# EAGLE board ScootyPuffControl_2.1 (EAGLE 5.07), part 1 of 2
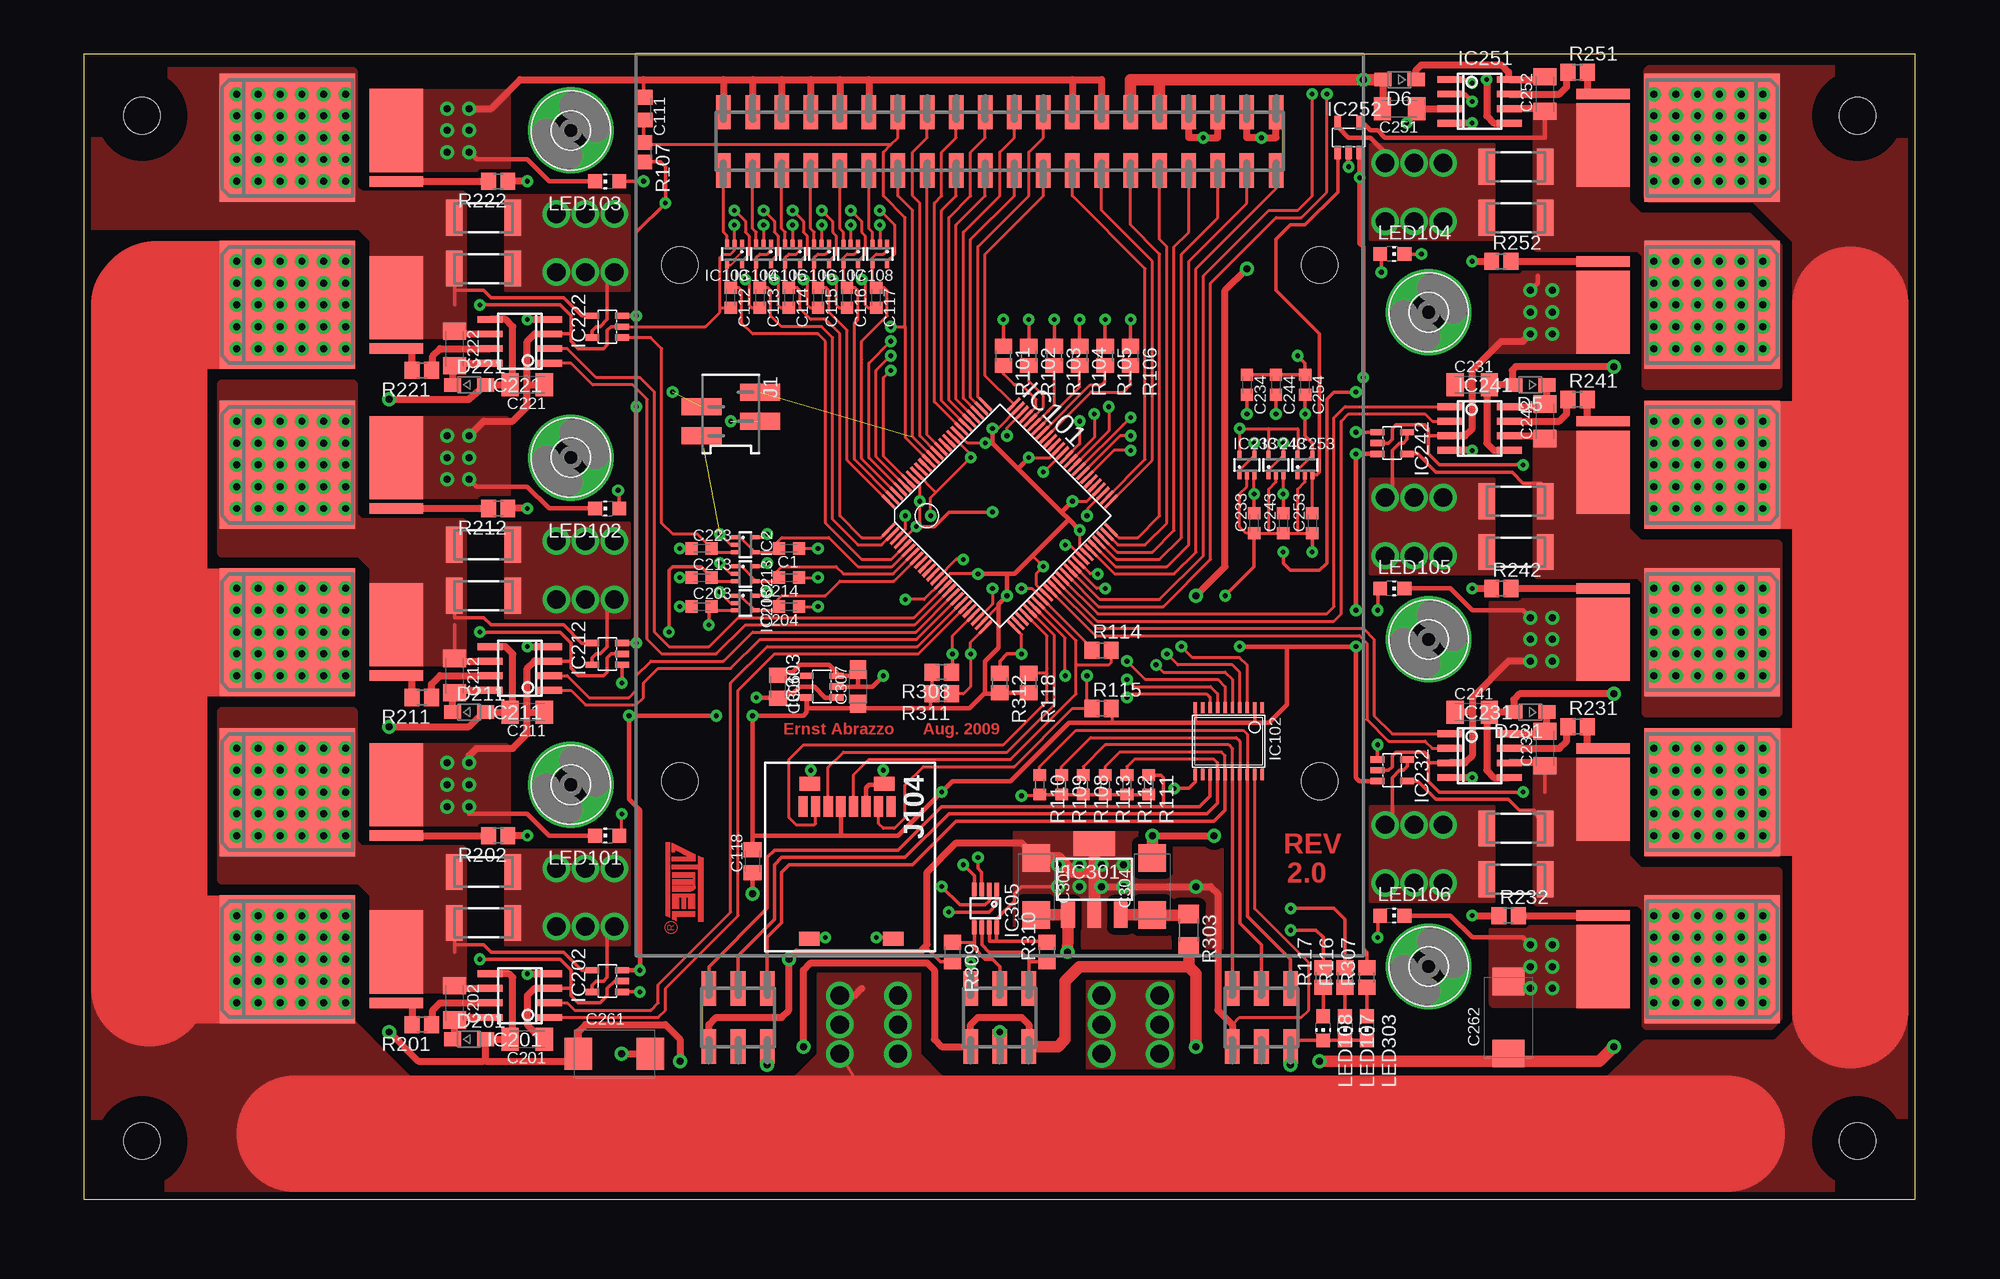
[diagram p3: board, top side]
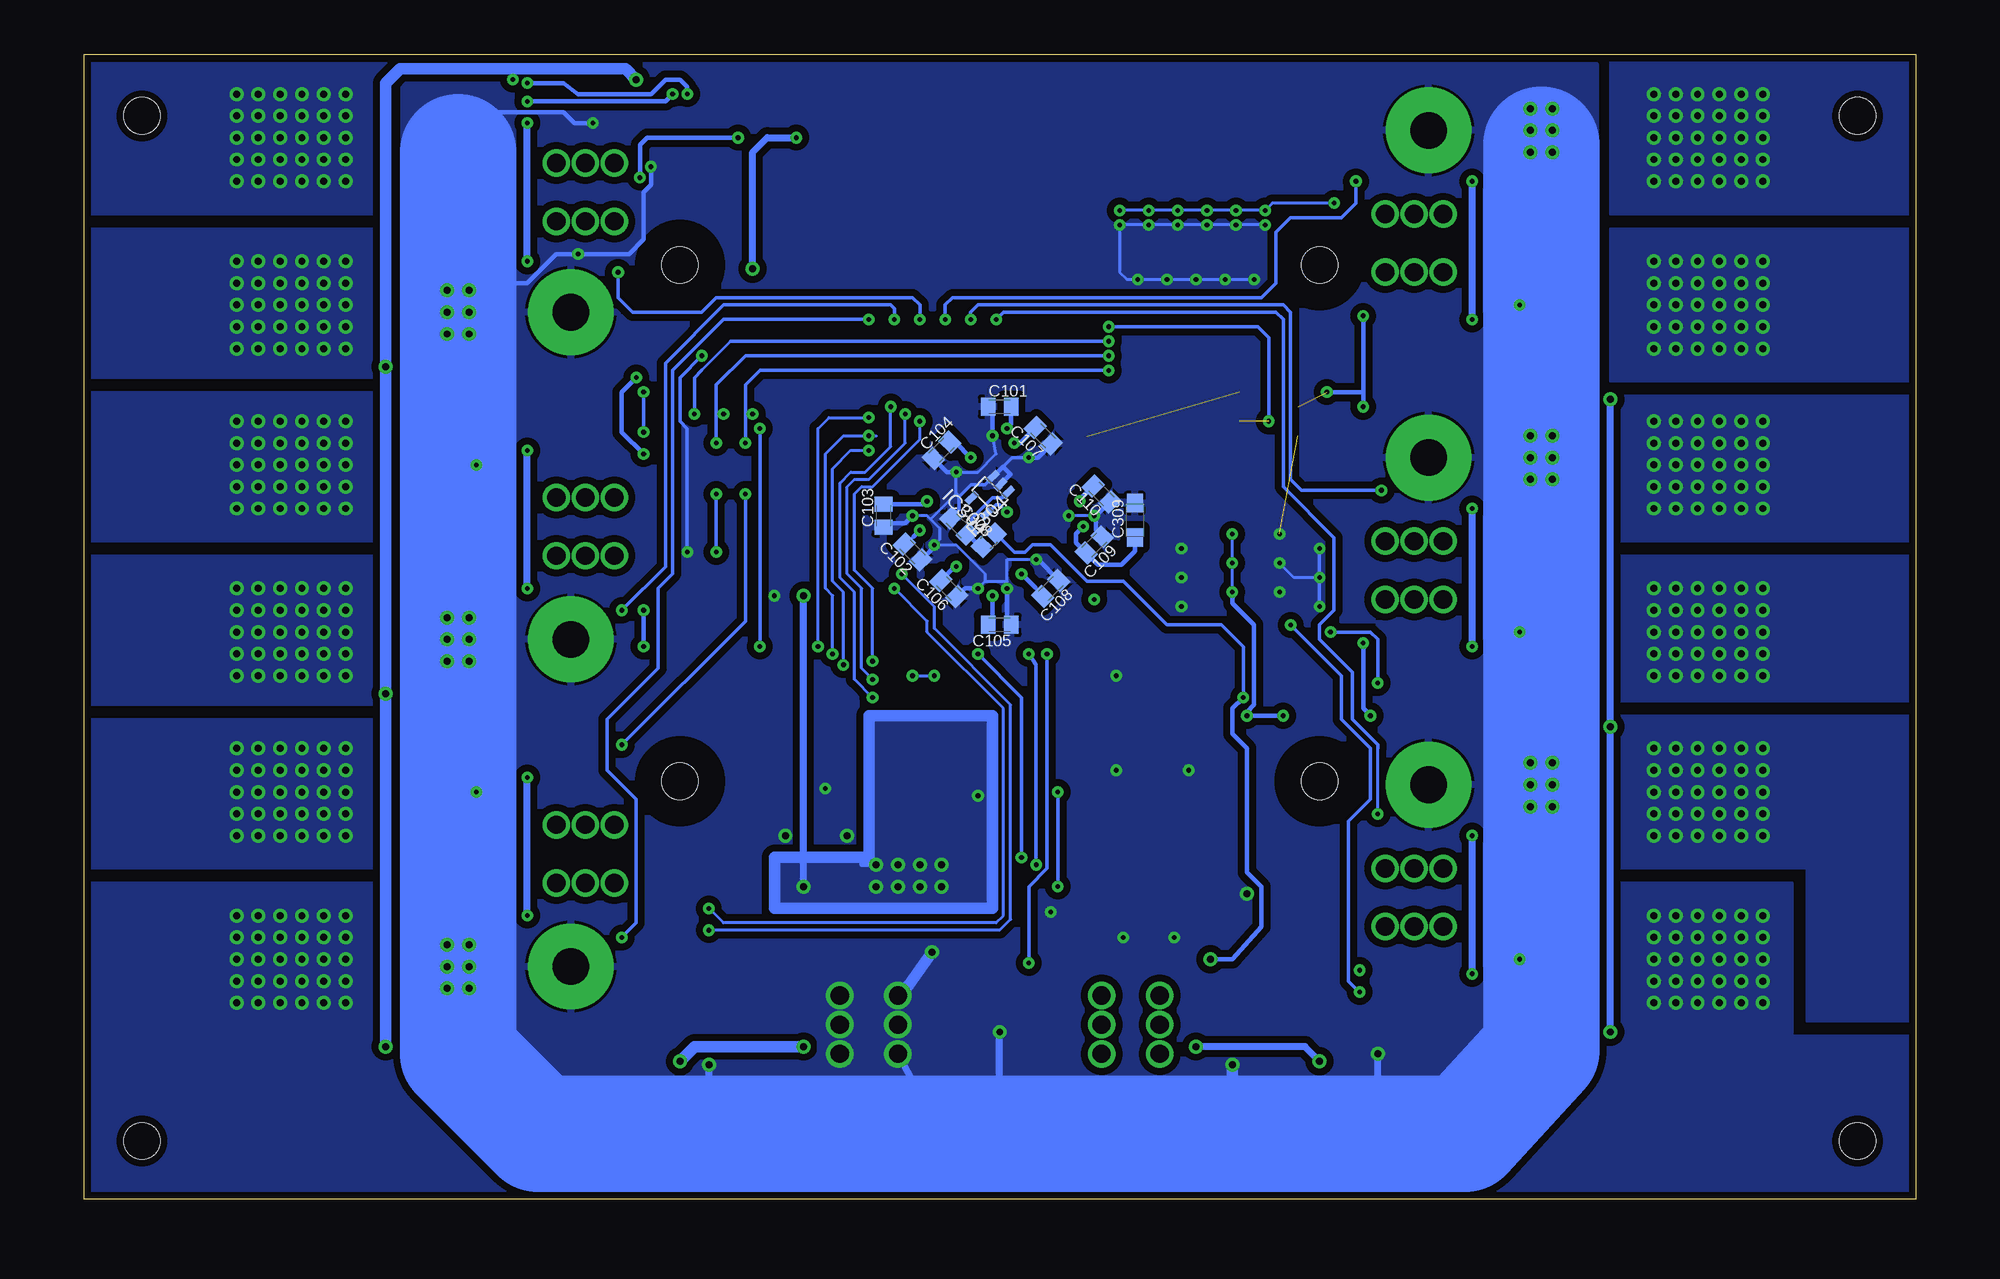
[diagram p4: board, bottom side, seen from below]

Size 160 x 100 mm. Coordinates in mm from the lower left corner, seen from the top.
Outline: 0,0 160,0 160,100 0,100 0,0
Copper layers (1*16): Top 0.035mm / dielectric 1.5mm / Bottom 0.035mm
Design rules "uni_ulm *": minimum track width 8mil, minimum drill 16mil, track to track 8mil, track to pad 8mil, pad to pad 8mil, via to via 8mil, smd to smd 8mil, copper to edge 20mil, drill to drill 8mil, minimum pad ring 12mil, minimum via ring 12mil, stop-mask expansion 4mil, vias tented up to drill 15mil, thermal gap 10mil
Holes 3.2 mm at 154.94,5.08 5.08,5.08 154.94,94.61 5.08,94.61
tRestrict: area 1.9,1.9 to 8.3,8.3; area 1.9,91.4 to 8.3,97.8; area 151.7,91.4 to 158.1,97.8; area 151.7,1.9 to 158.1,8.3

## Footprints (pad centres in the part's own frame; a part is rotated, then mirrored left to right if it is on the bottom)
C0603K = smd 1.05 x 1.08: 1 -0.875,0; 2 0.875,0
C0805K = smd 1.3 x 1.6: 1 -1,0; 2 1,0
C1206K = smd 1.5 x 2: 1 -1.5,0; 2 1.5,0
SMC_D = smd 2.4 x 2.8: + -3.15,0; - 3.15,0
SMC_C = smd 2.4 x 2.4: + -2.5,0; - 2.5,0
SMC_A = smd 1.6 x 1.4: + -1.5,0; - 1.5,0
SOD323-W = smd 1.5 x 1.2: A 1.45,0; C -1.45,0
3,2-PAD = drill 3.2 pad 7.5 round: B3,2 0,0
SC70-5L = smd 0.35 x 0.8: 1 -0.65,-0.85; 2 0,-0.85; 3 0.65,-0.85; 4 0.65,0.85; 5 -0.65,0.85
TQFP100 = smd 0.27 x 1.5: 1 -6,-7.75; 2 -5.5,-7.75; 3 -5,-7.75; 4 -4.5,-7.75; 5 -4,-7.75; 6 -3.5,-7.75; 7 -3,-7.75; 8 -2.5,-7.75; 9 -2,-7.75; 10 -1.5,-7.75; 11 -1,-7.75; 12 -0.5,-7.75; 13 0,-7.75; 14 0.5,-7.75; 15 1,-7.75; 16 1.5,-7.75; 17 2,-7.75; 18 2.5,-7.75; 19 3,-7.75; 20 3.5,-7.75; 21 4,-7.75; 22 4.5,-7.75; 23 5,-7.75; 24 5.5,-7.75; 25 6,-7.75; 51 6,7.75; 52 5.5,7.75; 53 5,7.75; 54 4.5,7.75; 55 4,7.75; 56 3.5,7.75; 57 3,7.75; 58 2.5,7.75; 59 2,7.75; 60 1.5,7.75; 61 1,7.75; 62 0.5,7.75; 63 0,7.75; 64 -0.5,7.75; 65 -1,7.75; 66 -1.5,7.75; 67 -2,7.75; 68 -2.5,7.75; 69 -3,7.75; 70 -3.5,7.75; 71 -4,7.75; 72 -4.5,7.75; 73 -5,7.75; 74 -5.5,7.75; 75 -6,7.75 | smd 1.5 x 0.27: 26 7.75,-6; 27 7.75,-5.5; 28 7.75,-5; 29 7.75,-4.5; 30 7.75,-4; 31 7.75,-3.5; 32 7.75,-3; 33 7.75,-2.5; 34 7.75,-2; 35 7.75,-1.5; 36 7.75,-1; 37 7.75,-0.5; 38 7.75,0; 39 7.75,0.5; 40 7.75,1; 41 7.75,1.5; 42 7.75,2; 43 7.75,2.5; 44 7.75,3; 45 7.75,3.5; 46 7.75,4; 47 7.75,4.5; 48 7.75,5; 49 7.75,5.5; 50 7.75,6; 76 -7.75,6; 77 -7.75,5.5; 78 -7.75,5; 79 -7.75,4.5; 80 -7.75,4; 81 -7.75,3.5; 82 -7.75,3; 83 -7.75,2.5; 84 -7.75,2; 85 -7.75,1.5; 86 -7.75,1; 87 -7.75,0.5; 88 -7.75,0; 89 -7.75,-0.5; 90 -7.75,-1; 91 -7.75,-1.5; 92 -7.75,-2; 93 -7.75,-2.5; 94 -7.75,-3; 95 -7.75,-3.5; 96 -7.75,-4; 97 -7.75,-4.5; 98 -7.75,-5; 99 -7.75,-5.5; 100 -7.75,-6
TSSOP20 = smd 0.305 x 0.991: 1 -2.925,-2.918; 2 -2.275,-2.918; 3 -1.625,-2.918; 4 -0.975,-2.918; 5 -0.325,-2.918; 6 0.325,-2.918; 7 0.975,-2.918; 8 1.625,-2.918; 9 2.275,-2.918; 10 2.925,-2.918; 11 2.925,2.918; 12 2.275,2.918; 13 1.625,2.918; 14 0.975,2.918; 15 0.325,2.918; 16 -0.325,2.918; 17 -0.975,2.918; 18 -1.625,2.918; 19 -2.275,2.918; 20 -2.925,2.918
SO08 = smd 0.6 x 2.2: 1 -1.905,-2.6; 2 -0.635,-2.6; 3 0.635,-2.6; 4 1.905,-2.6; 5 1.905,2.6; 6 0.635,2.6; 7 -0.635,2.6; 8 -1.905,2.6
SOT23-5L = smd 0.55 x 1.2: 1 -0.95,-1.3; 2 0,-1.3; 3 0.95,-1.3; 4 0.95,1.3; 5 -0.95,1.3
SOT223 = smd 1.219 x 2.235: 1 -2.311,-3.099; 2 0,-3.099; 3 2.311,-3.099 | smd 3.6 x 2.2: 4 0,3.099
SSOP08 = smd 0.4 x 1.2: 1 -1.005,-1.655; 2 -0.355,-1.655; 3 0.295,-1.655; 4 0.945,-1.655; 5 0.945,1.655; 6 0.295,1.655; 7 -0.355,1.655; 8 -1.005,1.655
SMDTOP4 = smd 1.5 x 3.5: 1 -1.905,2.54; 2 -0.635,-2.54; 3 0.635,2.54; 4 1.905,-2.54
SCOOTYPUFF_EXTENSION_SMT = smd 1.27 x 3: P$1 -24.13,-2.54; P$2 -24.13,2.54; P$3 -21.59,-2.54; P$4 -21.59,2.54; P$5 -19.05,-2.54; P$6 -19.05,2.54; P$7 -16.51,-2.54; P$8 -16.51,2.54; P$9 -13.97,-2.54; P$10 -13.97,2.54; P$11 -11.43,-2.54; P$12 -11.43,2.54; P$13 -8.89,-2.54; P$14 -8.89,2.54; P$15 -6.35,-2.54; P$16 -6.35,2.54; P$17 -3.81,-2.54; P$18 -3.81,2.54; P$19 -1.27,-2.54; P$20 -1.27,2.54; P$21 1.27,-2.54; P$22 1.27,2.54; P$23 3.81,-2.54; P$24 3.81,2.54; P$25 6.35,-2.54; P$26 6.35,2.54; P$27 8.89,-2.54; P$28 8.89,2.54; P$29 11.43,-2.54; P$30 11.43,2.54; P$31 13.97,-2.54; P$32 13.97,2.54; P$33 16.51,-2.54; P$34 16.51,2.54; P$35 19.05,-2.54; P$36 19.05,2.54; P$37 21.59,-2.54; P$38 21.59,2.54; P$39 24.13,-2.54; P$40 24.13,2.54 | hole 3.2: -27.94,-55.88; 27.94,-55.88; 27.94,-10.795; -27.94,-10.795
SL2X3G_SMD254@1 = smd 1.27 x 3: P$1 -2.54,-2.54; P$2 -2.54,2.54; P$3 0,-2.54; P$4 0,2.54; P$5 2.54,-2.54; P$6 2.54,2.54
JAE_ST1_MICOSD = smd 1.8 x 0.8: 1 0,-3.85; 2 0,-2.75; 3 0,-1.65; 4 0,-0.55; 5 0,0.55; 6 0,1.65; 7 0,2.75; 8 0,3.85 | smd 1.2 x 1.8: GND1 11.55,-3.3; GND2 11.55,4.05; GND3 -2,-3.25; GND4 -2,3.25
WE-SVB-6 = drill 1.6 pad 2.235 round: P$1 0,-2.54; P$2 2.54,-2.54; P$3 -2.54,-2.54; P$4 -2.54,2.54; P$5 0,2.54; P$6 2.54,2.54
SL2X3G_SMD254 = smd 1.27 x 3: 1 -2.54,-2.54; 2 -2.54,2.54; 3 0,-2.54; 4 0,2.54; 5 2.54,-2.54; 6 2.54,2.54
CHIP-LED0805 = smd 1.2 x 1.2: A 0,-1.05; C 0,1.05
R0805 = smd 1.3 x 1.5: 1 -0.85,0; 2 0.85,0
R0603 = smd 1 x 1.1: 1 -0.85,0; 2 0.85,0
R2010 = smd 1.44 x 3.12: P$1 -2.54,0; P$2 2.54,0
R1206 = smd 1.6 x 1.803: 1 -1.422,0; 2 1.422,0
D2PACK-7P = smd 11.176 x 11.836: D 0,0.635 | smd 0.914 x 4.699: G -3.81,-8.89 | smd 7.264 x 4.699: S 0.635,-8.89

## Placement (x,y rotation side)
C1  1µF  [C0603K]  61.59,56.83 180 top
C101  100n  [C0805K]  80.01,69.22 0 bottom
C102  100n  [C0805K]  87.63,56.52 135 bottom
C103  100n  [C0805K]  90.17,59.69 90 bottom
C104  100n  [C0805K]  85.09,65.41 45 bottom
C105  100n  [C0805K]  80.01,50.16 180 bottom
C106  100n  [C0805K]  84.45,53.34 135 bottom
C107  100n  [C0805K]  76.2,66.67 135 bottom
C108  100n  [C0805K]  75.56,53.34 225 bottom
C109  100n  [C0805K]  71.75,57.15 225 bottom
C110  100n  [C0805K]  71.12,61.59 135 bottom
C111  100n  [C0805K]  48.9,95.25 270 top
C112  [C0603K]  56.52,78.74 270 top
C113  [C0603K]  59.05,78.74 270 top
C114  [C0603K]  61.59,78.74 270 top
C115  [C0603K]  64.14,78.74 270 top
C116  [C0603K]  66.67,78.74 270 top
C117  [C0603K]  69.22,78.74 270 top
C118  100n  [C0805K]  58.42,29.53 90 top
C201  1µF, 16V  [C1206K]  38.73,13.97 180 top
C202  1µF  [C1206K]  32.38,17.14 270 top
C203  100pF  [C0603K]  53.98,51.75 0 top
C204  1µF  [C0603K]  61.59,51.75 180 top
C211  1µF, 16V  [C1206K]  38.73,42.55 180 top
C212  1µF, 16V  [C1206K]  32.38,45.72 270 top
C213  100pF  [C0603K]  53.98,54.29 0 top
C214  1µF  [C0603K]  61.59,54.29 180 top
C221  1µF,16V  [C1206K]  38.73,71.12 180 top
C222  1µF, 16V  [C1206K]  32.38,74.3 270 top
C223  100pF  [C0603K]  53.98,56.83 0 top
C231  1µF,16V  [C1206K]  121.28,71.12 0 top
C232  1µF,16V  [C1206K]  127.64,39.37 90 top
C233  100pF  [C0603K]  102.23,59.05 90 top
C234  1µF  [C0603K]  101.6,71.12 270 top
C241  1µF,16V  [C1206K]  121.28,42.55 0 top
C242  1µF,16V  [C1206K]  127.64,67.94 90 top
C243  100pF  [C0603K]  104.78,59.05 90 top
C244  1µF  [C0603K]  104.14,71.12 270 top
C251  1µF,16V  [C1206K]  114.94,95.25 180 top
C252  1µF,16V  [C1206K]  127.64,96.52 90 top
C253  100pF  [C0603K]  107.31,59.05 90 top
C254  1µF  [C0603K]  106.68,71.12 270 top
C261  [SMC_D]  46.35,12.7 0 top
C262  [SMC_D]  124.46,15.88 90 top
C304  10µF, 16V, Tantal (C)  [SMC_C]  93.34,27.3 90 top
C305  10µF-100µF, 6.3V,Tantal (C)  [SMC_C]  83.19,27.3 270 top
C306  1µ  [C0805K]  60.64,44.77 270 top
C307  4,7µF Tantal  [SMC_A]  67.63,44.77 90 top
C308  1µ  [C0805K]  83.56,58.81 315 bottom
C309  4,7µF Tantal  [SMC_A]  68.2,59.3 90 bottom
D5  BAT54J  [SOD323-W]  126.36,71.12 180 top
D6  BAT54J  [SOD323-W]  114.94,97.79 180 top
D201  BAT54J  [SOD323-W]  33.66,13.97 0 top
D211  BAT54J  [SOD323-W]  33.66,42.55 0 top
D221  BAT54J  [SOD323-W]  33.66,71.12 0 top
D231  BAT54J  [SOD323-W]  126.36,42.55 180 top
H2  MOUNT-PAD-ROUND3.2  [3,2-PAD]  42.55,36.2 0 top
H3  MOUNT-PAD-ROUND3.2  [3,2-PAD]  42.55,64.77 0 top
H4  MOUNT-PAD-ROUND3.2  [3,2-PAD]  42.55,93.34 0 top
H8  MOUNT-PAD-ROUND3.2  [3,2-PAD]  117.47,20.32 0 top
H9  MOUNT-PAD-ROUND3.2  [3,2-PAD]  117.47,48.9 0 top
H10  MOUNT-PAD-ROUND3.2  [3,2-PAD]  117.47,77.47 0 top
IC2  AD8541-SC70  [SC70-5L]  57.78,57.15 270 top
IC101  ATXMEGA-A1  [TQFP100]  80.01,59.69 315 top
IC102  TXS0108PW  [TSSOP20]  100.01,40.01 180 top
IC103  AD8541-SC70  [SC70-5L]  56.83,82.55 180 top
IC104  AD8541-SC70  [SC70-5L]  59.37,82.55 180 top
IC105  AD8541-SC70  [SC70-5L]  61.91,82.55 180 top
IC106  AD8541-SC70  [SC70-5L]  64.45,82.55 180 top
IC107  AD8541-SC70  [SC70-5L]  66.99,82.55 180 top
IC108  AD8541-SC70  [SC70-5L]  69.53,82.55 180 top
IC201  IRS2186S  [SO08]  38.1,17.78 90 top
IC202  INA196  [SOT23-5L]  45.72,19.05 90 top
IC203  AD8541-SC70  [SC70-5L]  57.78,52.07 270 top
IC211  IRS2186S  [SO08]  38.1,46.35 90 top
IC212  INA196  [SOT23-5L]  45.72,47.62 90 top
IC213  AD8541-SC70  [SC70-5L]  57.78,54.61 270 top
IC221  IRS2186S  [SO08]  38.1,74.93 90 top
IC222  INA196  [SOT23-5L]  45.72,76.2 90 top
IC231  IRS2186S  [SO08]  121.92,38.73 270 top
IC232  INA196  [SOT23-5L]  114.3,37.47 270 top
IC233  AD8541-SC70  [SC70-5L]  101.6,64.14 0 top
IC241  IRS2186S  [SO08]  121.92,67.31 270 top
IC242  INA196  [SOT23-5L]  114.3,66.04 270 top
IC243  AD8541-SC70  [SC70-5L]  104.14,64.14 0 top
IC251  IRS2186S  [SO08]  121.92,95.89 270 top
IC252  INA196  [SOT23-5L]  110.49,92.71 0 top
IC253  AD8541-SC70  [SC70-5L]  106.68,64.14 0 top
IC301  LM1117-50  [SOT223]  88.27,27.94 0 top
IC303  TPS76933  [SOT23-5L]  64.45,44.77 90 top
IC304  TPS76933  [SOT23-5L]  80.87,61.5 135 bottom
IC305  PCA9306DCT  [SSOP08]  78.74,25.4 180 top
J1  AVR-PDIMM04  [SMDTOP4]  56.52,68.58 270 top
J100  SCOOTYPUFF_EXTENSION  [SCOOTYPUFF_EXTENSION_SMT]  80.01,92.39 0 top
J102  SL6X2_SL  [SL2X3G_SMD254@1]  57.15,15.88 180 top
J103  SL6X2_SL  [SL2X3G_SMD254@1]  102.87,15.88 180 top
J104  MICRO_SD_ST1  [JAE_ST1_MICOSD]  66.67,34.29 270 top
J301  WE-SVB-6  [WE-SVB-6]  68.58,15.24 90 top
J302  WE-SVB-6  [WE-SVB-6]  91.44,15.24 90 top
J303  SL3X2_SL  [SL2X3G_SMD254]  80.01,15.88 180 top
J_U1  WE-SVB-6  [WE-SVB-6]  43.81,26.35 180 top
J_U2  WE-SVB-6  [WE-SVB-6]  116.2,30.16 0 top
J_V1  WE-SVB-6  [WE-SVB-6]  43.81,54.93 0 top
J_V2  WE-SVB-6  [WE-SVB-6]  116.2,58.74 0 top
J_W1  WE-SVB-6  [WE-SVB-6]  43.81,83.5 0 top
J_W2  WE-SVB-6  [WE-SVB-6]  116.2,87.95 0 top
LED101  [CHIP-LED0805]  45.72,31.75 90 top
LED102  [CHIP-LED0805]  45.72,60.33 90 top
LED103  [CHIP-LED0805]  45.72,88.9 90 top
LED104  [CHIP-LED0805]  114.3,82.55 270 top
LED105  [CHIP-LED0805]  114.3,53.34 270 top
LED106  [CHIP-LED0805]  114.3,24.77 270 top
LED107  [CHIP-LED0805]  110.17,14.92 180 top
LED108  [CHIP-LED0805]  108.27,14.92 180 top
LED303  [CHIP-LED0805]  112.08,14.92 180 top
R101  [R0805]  80.33,73.66 270 top
R102  [R0805]  82.55,73.66 270 top
R103  [R0805]  84.77,73.66 270 top
R104  [R0805]  87,73.66 270 top
R105  [R0805]  89.22,73.66 270 top
R106  [R0805]  91.44,73.66 270 top
R107  10k  [R0805]  48.9,91.44 270 top
R108  10k  [R0603]  87.31,36.2 270 top
R109  10k  [R0603]  85.41,36.2 270 top
R110  10k  [R0603]  83.5,36.2 270 top
R111  10k  [R0603]  93.03,36.2 270 top
R112  10k  [R0603]  91.12,36.2 270 top
R113  10k  [R0603]  89.22,36.2 270 top
R114  50k  [R0805]  88.9,47.94 0 top
R115  50k  [R0805]  88.9,42.86 0 top
R116  [R0805]  110.17,19.37 90 top
R117  [R0805]  108.27,19.37 90 top
R118  50k  [R0805]  82.55,45.09 270 top
R201  2R  [R0805]  29.53,15.24 180 top
R202  2R  [R0805]  36.2,31.75 180 top
R203  4mR  [R2010]  34.92,28.57 0 top
R204  4mR  [R2010]  34.92,24.13 0 top
R211  2R  [R0805]  29.53,43.81 180 top
R212  2R  [R0805]  36.2,60.33 180 top
R213  4mR  [R2010]  34.92,52.7 0 top
R214  4mR  [R2010]  34.92,57.15 0 top
R221  2R  [R0805]  29.53,72.39 180 top
R222  2R  [R0805]  36.2,88.9 180 top
R223  4mR  [R2010]  34.92,85.72 0 top
R224  4mR  [R2010]  34.92,81.28 0 top
R231  2R  [R0805]  130.49,41.27 0 top
R232  2R  [R0805]  124.46,24.77 0 top
R233  4mR  [R2010]  125.09,32.38 180 top
R234  4mR  [R2010]  125.09,27.94 180 top
R241  2R  [R0805]  130.49,69.85 0 top
R242  2R  [R0805]  123.83,53.34 0 top
R243  4mR  [R2010]  125.09,56.52 180 top
R244  4mR  [R2010]  125.09,60.96 180 top
R251  2R  [R0805]  130.49,98.42 0 top
R252  2R  [R0805]  123.83,81.92 0 top
R253  4mR  [R2010]  125.09,85.72 180 top
R254  4mR  [R2010]  125.09,90.17 180 top
R303  10  [R1206]  96.52,23.5 270 top
R304  100  [R0805]  80.96,57.55 45 bottom
R307  [R0805]  112.08,19.37 90 top
R308  10k  [R0805]  74.93,46.04 180 top
R309  1k  [R0805]  75.88,21.59 270 top
R310  1k  [R0805]  84.14,21.59 90 top
R311  330R  [R0805]  74.93,44.13 180 top
R312  330R  [R0805]  80.01,45.09 270 top
T8  IRLS3036-7  [D2PACK-7P]  141.6,20.95 270 top
T201  IRLS3036-7  [D2PACK-7P]  18.41,20.95 90 top
T202  IRLS3036-7  [D2PACK-7P]  18.41,35.56 90 top
T211  IRLS3036-7  [D2PACK-7P]  18.41,49.53 90 top
T212  IRLS3036-7  [D2PACK-7P]  18.41,64.14 90 top
T221  IRLS3036-7  [D2PACK-7P]  18.41,78.11 90 top
T222  IRLS3036-7  [D2PACK-7P]  18.41,92.71 90 top
T231  IRLS3036-7  [D2PACK-7P]  141.6,35.56 270 top
T241  IRLS3036-7  [D2PACK-7P]  141.6,64.14 270 top
T242  IRLS3036-7  [D2PACK-7P]  141.6,49.53 270 top
T251  IRLS3036-7  [D2PACK-7P]  141.6,92.71 270 top
T252  IRLS3036-7  [D2PACK-7P]  141.6,78.11 270 top
U$7  [LOGO_TOP]  50.8,31.11 270 top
